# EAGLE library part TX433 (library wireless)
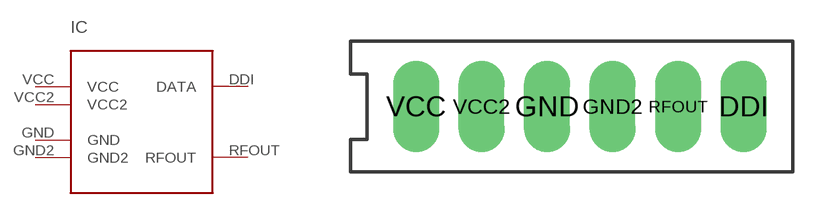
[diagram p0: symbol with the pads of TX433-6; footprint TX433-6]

Designator prefix IC

## TX433  [TX433-6]
DDI  DATA  in
GND  GND  pwr
GND2  GND2  pwr
RFOUT  RFOUT  out
VCC  VCC  pwr
VCC2  VCC2  pwr

## Footprint TX433-6 (pad centres in mm)
drill 1.016 pad 1.778 long: DDI 12.7,0; GND 5.08,0; GND2 7.62,0; RFOUT 10.16,0; VCC 0,0; VCC2 2.54,0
